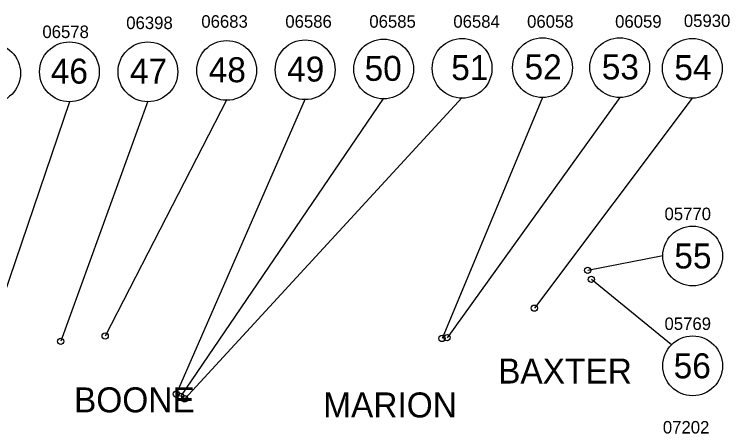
# Model space of a CAD drawing. Extents: x -13171 to 18763, y -8840 to 11152.
# Drawn here: x 10714 to 17581, y -779 to 3247 of the extents above; entities that cross this region are included whole.
import ezdxf

# ---------------------------------------------------------------- set-up
doc = ezdxf.new("R2010")
doc.units = 0
for name, color, linetype in [('Level 2', 7, 'Continuous'), ('Level 48', 7, 'Continuous'), ('Level 50', 7, 'Continuous')]:
    doc.layers.add(name, color=color, linetype=linetype)

msp = doc.modelspace()

# ---------------------------------------------------------------- linework, layer by layer
at = {"layer": 'Level 48'}
for p, q in [((11242.8, 2408.1), (10177.1, -727.3)), ((11996.1, 2414.9), (11158.9, 108.8)), ((12752.6, 2428.3), (11585.9, 158.6)), ((13505.8, 2435), (12268.6, -398.6)), ((14259.1, 2441.8), (12310, -420.4)), ((15012.3, 2448.5), (12349.1, -443.5)), ((15784.2, 2448.5), (14819.5, 135.6)), ((16525.5, 2448.5), (14867.9, 143.1)), ((17222.3, 2441.8), (15705.8, 426.4)), ((16938.6, 927.5), (16217.8, 788.9)), ((17022.7, 75.8), (16253.9, 702.8))]:
    msp.add_line(p, q, dxfattribs=at)
for centre, radius in [((15784.2, 2735.4), 286.9), ((16525.5, 2735.4), 286.9), ((10486.3, 2681.6), 286.9), ((11242.8, 2695), 286.9), ((11996.1, 2695), 286.9), ((12752.6, 2708.5), 286.9), ((13505.8, 2715.2), 286.9), ((14259.1, 2721.9), 286.9), ((15012.3, 2728.7), 286.9), ((17222.3, 2728.7), 286.9), ((17225.5, 927.5), 286.9), ((16217.8, 788.9), 30.2), ((16253.9, 702.8), 30.2), ((15705.8, 426.4), 30.2), ((11158.9, 108.8), 30.2), ((11585.9, 158.6), 30.2), ((14819.5, 135.6), 30.2), ((14867.9, 143.1), 30.2), ((17225.5, -127), 286.9), ((12268.6, -398.6), 30.2), ((12310, -420.4), 30.2), ((12349.1, -443.5), 30.2)]:
    msp.add_circle(centre, radius, dxfattribs=at)

# ---------------------------------------------------------------- texts
at = {"layer": 'Level 2'}
for s, p in [('BAXTER', (15358, -297.1)), ('BOONE', (11286.6, -573.8)), ('MARION', (13678.6, -622.8))]:
    msp.add_text(s, height=240, dxfattribs=at).set_placement(p)
at = {"layer": 'Level 48'}
for s, p in [('46', (11063.7, 2581.8)), ('47', (11823.6, 2581.8)), ('48', (12580.1, 2595.2)), ('49', (13332.4, 2601.9)), ('50', (14076.2, 2608.7)), ('51', (14907.8, 2615.4)), ('52', (15611.7, 2622.1)), ('53', (16353, 2622.1)), ('54', (17049.8, 2615.4)), ('55', (17049.8, 807.5)), ('56', (17043.2, -247))]:
    msp.add_text(s, height=240, dxfattribs=at).set_placement(p)
at = {"layer": 'Level 50'}
for s, p in [('06683', (12509, 3118.6)), ('06586', (13315.4, 3118.6)), ('06585', (14121.8, 3118.6)), ('06584', (14928.2, 3118.6)), ('06058', (15636.1, 3118.6)), ('06059', (16481.4, 3118.6)), ('05930', (17141.2, 3125.6)), ('06398', (11788.3, 3105.6)), ('06578', (10983.3, 3019.5)), ('05770', (16955.5, 1271.5)), ('05769', (16955.5, 217)), ('07202', (16939.7, -776.9))]:
    msp.add_text(s, height=120, dxfattribs=at).set_placement(p)

doc.saveas('drawing.dxf')
